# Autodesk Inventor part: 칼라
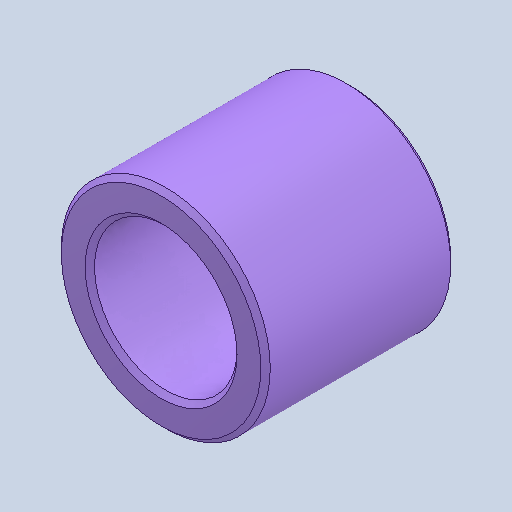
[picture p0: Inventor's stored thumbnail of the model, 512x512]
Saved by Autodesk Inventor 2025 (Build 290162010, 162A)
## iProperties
Created: 2024-07
Part Number: 칼라
Material: 스테인리스강
Document SubType Name: Modeling
Designer: 학생
Density: 8.08 g/cm^3
Appearance: 기본값
Author: jhkim
Sending System: Autodesk Inventor 2025
Preprocessor: ST-DEVELOPER v20
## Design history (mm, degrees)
feature "솔리드1"
node "솔리드2"
